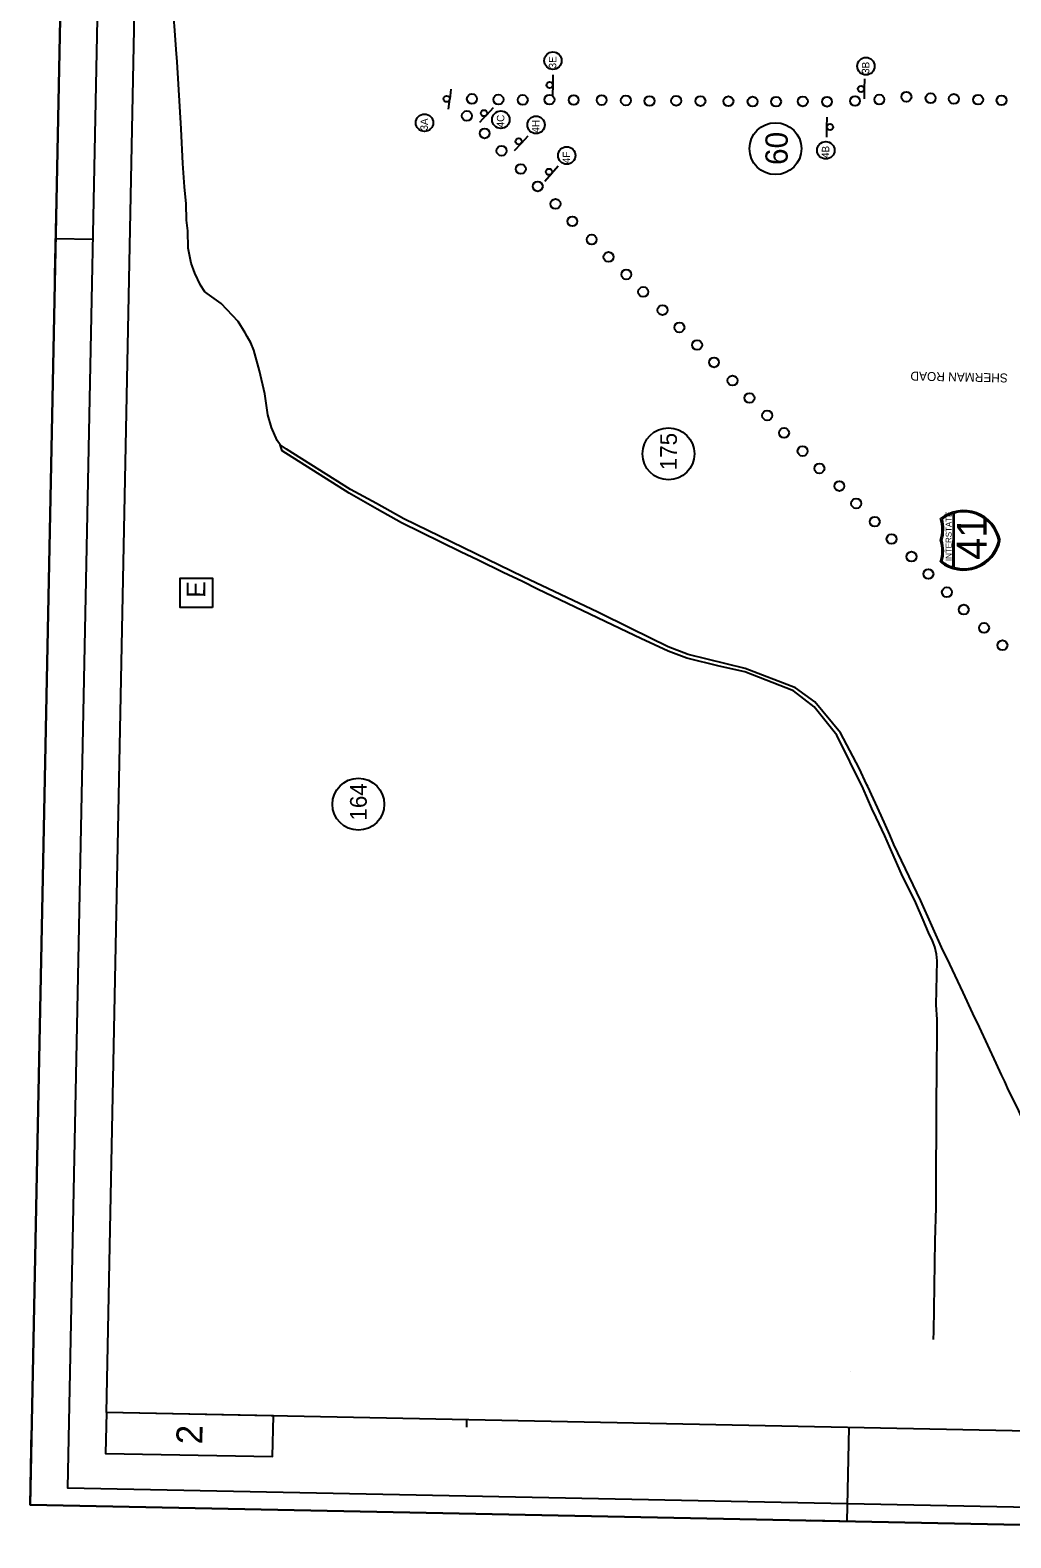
# Model space of a CAD drawing. Extents: x 335726 to 369746, y 119154 to 200788.
# Drawn here: x 335726 to 355527, y 119154 to 149591 of the extents above; entities that cross this region are included whole.
import ezdxf

# ---------------------------------------------------------------- set-up
doc = ezdxf.new("R2010")
doc.units = 0
for name, color, linetype in [('CA-TEXT', 7, 'Continuous'), ('Level 1', 7, 'Continuous'), ('Level 58', 7, 'Continuous'), ('P_RDWY_Text', 7, 'Continuous'), ('PLT_Sheet_Border', 7, 'Continuous'), ('PLT_Sheet_Info', 7, 'Continuous'), ('SIGNS-POLES', 7, 'Continuous')]:
    doc.layers.add(name, color=color, linetype=linetype)

msp = doc.modelspace()

# ---------------------------------------------------------------- linework, layer by layer
at = {"layer": 'CA-TEXT'}
for p, q in [((350774, 147199), (350774, 147199)), ((348614, 141038), (348614, 141038)), ((354359, 139835), (354356, 138750)), ((354381, 138743), (354384, 139842)), ((339073, 138244), (339073, 138244)), ((342353, 133964), (342353, 133964))]:
    msp.add_line(p, q, dxfattribs=at)
msp.add_lwpolyline([(339408, 137936), (338752, 137939), (338754, 138528), (339410, 138525)], close=True, dxfattribs=at)
for centre, radius in [((346281, 148975), 176), ((352601, 148864), 176), ((345230, 147784), 176), ((343688, 147721), 176), ((345941, 147679), 176), ((350774, 147199), 524), ((351791, 147166), 176), ((346560, 147061), 176), ((348614, 141038), 524), ((342353, 133964), 524)]:
    msp.add_circle(centre, radius, dxfattribs=at)
for centre, radius, start, end in [((353391, 139514), 750, 342.8553, 16.8422), ((354573, 139142), 750, 11.3832, 128.1773), ((353391, 139514), 775, 343.4192, 15.5586), ((354573, 139142), 725, 107.1012, 126.8422), ((354573, 139142), 725, 11.7868, 105.0434), ((353390, 139076), 750, 342.8502, 16.8372), ((354573, 139442), 750, 231.5152, 348.3093), ((353390, 139076), 775, 344.1339, 16.2733), ((354573, 139442), 725, 254.649, 347.9057), ((354573, 139442), 725, 232.8503, 252.5912)]:
    msp.add_arc(centre, radius, start, end, dxfattribs=at)
at = {"layer": 'Level 1'}
for points in [[(338749, 148053), (338695, 148954), (338672, 149198), (338639, 149680), (338594, 150149), (338584, 150443), (338543, 150754)], [(338908, 145539), (338885, 145752), (338875, 146084), (338841, 146428), (338808, 146897), (338777, 147597), (338749, 148053)], [(339166, 144443), (339050, 144682), (338977, 144889), (338917, 145189), (338908, 145539)], [(339253, 144311), (339166, 144443)], [(340066, 143483), (339923, 143711), (339582, 144071), (339253, 144311)], [(340358, 142714), (340243, 143134), (340182, 143278), (340108, 143404), (340066, 143483)], [(340466, 142250), (340358, 142714)], [(340776, 141222), (340714, 141304), (340597, 141568), (340525, 141825), (340466, 142250)], [(342197, 140321), (340900, 141134), (340776, 141222)], [(343270, 139728), (342722, 140036), (342197, 140321)], [(347853, 137515), (347187, 137839), (345680, 138553), (343270, 139728)], [(350160, 136706), (349012, 136985), (348607, 137139), (347853, 137515)], [(351176, 136316), (350160, 136706)], [(352087, 135407), (351567, 136031), (351176, 136316)], [(352640, 134321), (352622, 134359), (352462, 134691), (352087, 135407)], [(353161, 133148), (353081, 133348), (352910, 133737), (352640, 134321)], [(353707, 132011), (353161, 133148)], [(354762, 129739), (354566, 130160), (354240, 130850), (354154, 131020), (353707, 132011)], [(355807, 127497), (355688, 127775), (355615, 127932), (355479, 128195), (355406, 128365), (355338, 128503), (355228, 128735), (354891, 129463), (354762, 129739)]]:
    msp.add_lwpolyline(points, dxfattribs=at)
at = {"layer": 'Level 58'}
for points in [[(342164, 140243), (340812, 141097), (340776, 141222)], [(343227, 139643), (342734, 139923), (342164, 140243)], [(347790, 137440), (345971, 138307), (345666, 138459), (345274, 138644), (344770, 138892), (344415, 139058), (343227, 139643)], [(350153, 136637), (349635, 136748), (348986, 136911), (348606, 137051), (348058, 137313), (347790, 137440)], [(351138, 136254), (350153, 136637)], [(352012, 135358), (351554, 135931), (351138, 136254)], [(352546, 134284), (352012, 135358)], [(353122, 133006), (352981, 133324), (352809, 133695), (352723, 133877), (352546, 134284)], [(353607, 131975), (353318, 132559), (353122, 133006)], [(354040, 130802), (354029, 130940), (353992, 131084), (353944, 131209), (353864, 131372), (353754, 131630), (353607, 131975)], [(354019, 129915), (354040, 130802)], [(354030, 128327), (354041, 129621), (354019, 129915)], [(354019, 125821), (354028, 128158), (354030, 128327)], [(353971, 123321), (354000, 125152), (354019, 125821)], [(353967, 123157), (353971, 123321)]]:
    msp.add_lwpolyline(points, dxfattribs=at)
at = {"layer": 'P_RDWY_Text'}
msp.add_lwpolyline([(335726, 119818), (336753, 170808), (369746, 170144), (368719, 119154)], close=True, dxfattribs=at)
at = {"layer": 'PLT_Sheet_Border'}
for points in [[(368719, 119154), (369746, 170144), (336753, 170808), (335726, 119818)], [(367976, 119529), (368976, 169169), (337483, 169803), (336483, 120163)]]:
    msp.add_lwpolyline(points, close=True, dxfattribs=at)
at = {"layer": 'PLT_Sheet_Info'}
for p, q in [((337264, 121685), (338215, 168926)), ((336226, 144638), (336256, 146138)), ((336241, 145388), (336991, 145373)), ((352283, 122508), (352283, 122508)), ((367258, 121081), (337264, 121685)), ((344537, 121539), (344534, 121389)), ((335726, 119818), (335756, 121318)), ((352222, 119486), (352261, 121383)), ((337225, 119788), (335726, 119818)), ((352972, 119471), (351473, 119501))]:
    msp.add_line(p, q, dxfattribs=at)
msp.add_lwpolyline([(337264, 121685), (337247, 120860), (340621, 120793), (340638, 121617)], close=True, dxfattribs=at)
for centre in [(344646, 148204), (345182, 148191), (345672, 148184), (346211, 148188), (346700, 148181), (347265, 148179), (347754, 148172), (348231, 148161), (348770, 148166), (349259, 148159), (349824, 148156), (350313, 148149), (350787, 148148), (351326, 148153), (351815, 148146), (352381, 148160), (352871, 148191), (353418, 148246), (353907, 148218), (354377, 148203), (354866, 148188), (355340, 148174), (344544, 147861), (344902, 147507), (345243, 147156), (345633, 146788), (345974, 146437), (346333, 146083), (346673, 145732), (347064, 145364), (347404, 145013), (347763, 144659), (348104, 144308), (348494, 143940), (348835, 143589), (349193, 143235), (349534, 142884), (349908, 142517), (350249, 142166), (350607, 141812), (350948, 141461), (351322, 141093), (351662, 140742), (352064, 140387), (352405, 140036), (352779, 139669), (353119, 139318), (353521, 138963), (353862, 138612), (354236, 138244), (354576, 137893), (354986, 137525), (355357, 137173)]:
    msp.add_circle(centre, 100, dxfattribs=at)
at = {"layer": 'SIGNS-POLES'}
for p, q in [((346282, 148688), (346279, 148486)), ((352570, 148610), (352567, 148407)), ((344223, 148401), (344197, 148200)), ((346278, 148484), (346274, 148282)), ((352566, 148406), (352562, 148203)), ((344196, 148198), (344169, 147998)), ((345075, 148023), (344938, 147874)), ((344936, 147874), (344798, 147726)), ((351810, 147431), (351812, 147633)), ((351814, 147635), (351818, 147837)), ((345777, 147454), (345639, 147305)), ((345637, 147305), (345499, 147158)), ((346386, 146846), (346254, 146692)), ((346252, 146692), (346119, 146539))]:
    msp.add_line(p, q, dxfattribs=at)
for centre in [(346215, 148483), (344134, 148204), (352503, 148405), (344889, 147915), (351876, 147636), (345590, 147346), (346203, 146731)]:
    msp.add_circle(centre, 62.6, dxfattribs=at)

# ---------------------------------------------------------------- texts
at = {"layer": 'CA-TEXT'}
for s, height, rotation, p in [('3E', 150, 88.8468, (346347, 148817)), ('3B', 150, 88.8468, (352667, 148706)), ('3A', 150, 88.8468, (343754, 147563)), ('4C', 150, 88.8468, (345296, 147626)), ('4H', 150, 88.8468, (346007, 147521)), ('60', 450, 89.767, (351020, 146868)), ('4F', 150, 88.8468, (346625, 146903)), ('4B', 150, 88.8468, (351857, 147008)), ('SHERMAN ROAD', 180, 178.8468, (355467, 142658)), ('175', 337.5, 89.767, (348782, 140707)), ('INTERSTATE', 120, 89.8462, (354329, 138873)), ('41', 599.8, 89.8462, (355035, 138898)), ('E', 375, 89.767, (339260, 138130)), ('164', 337.5, 89.767, (342520, 133634))]:
    msp.add_text(s, height=height, rotation=rotation, dxfattribs=at).set_placement(p)
at = {"layer": 'PLT_Sheet_Info'}
msp.add_text('2', height=525, rotation=88.8462, dxfattribs=at).set_placement((339201, 121037))

doc.saveas('drawing.dxf')
